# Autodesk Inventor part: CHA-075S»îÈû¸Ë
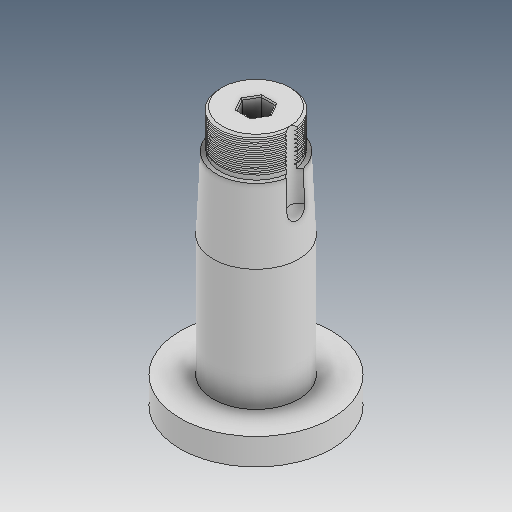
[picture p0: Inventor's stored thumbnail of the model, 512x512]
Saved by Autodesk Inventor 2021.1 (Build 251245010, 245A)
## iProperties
Created: 2019-05
Part Number: CHA-075S»îÈû¸Ë
Material: Ogólny
Document SubType Name: Modeling
Designer: user
Density: 1 g/cm^3
Appearance: Domyślna
Author: user
Revision Number: ÈÎºÎ
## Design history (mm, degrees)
feature "ÊäÈë1"
node "Bryła1"
